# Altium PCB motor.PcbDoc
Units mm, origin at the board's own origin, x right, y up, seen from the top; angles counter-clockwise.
Board outline 22.48 x 19.69 mm, 2 copper layers (Top Layer, Bottom Layer); 9 components, 6 nets, 20 pads, 0 vias.
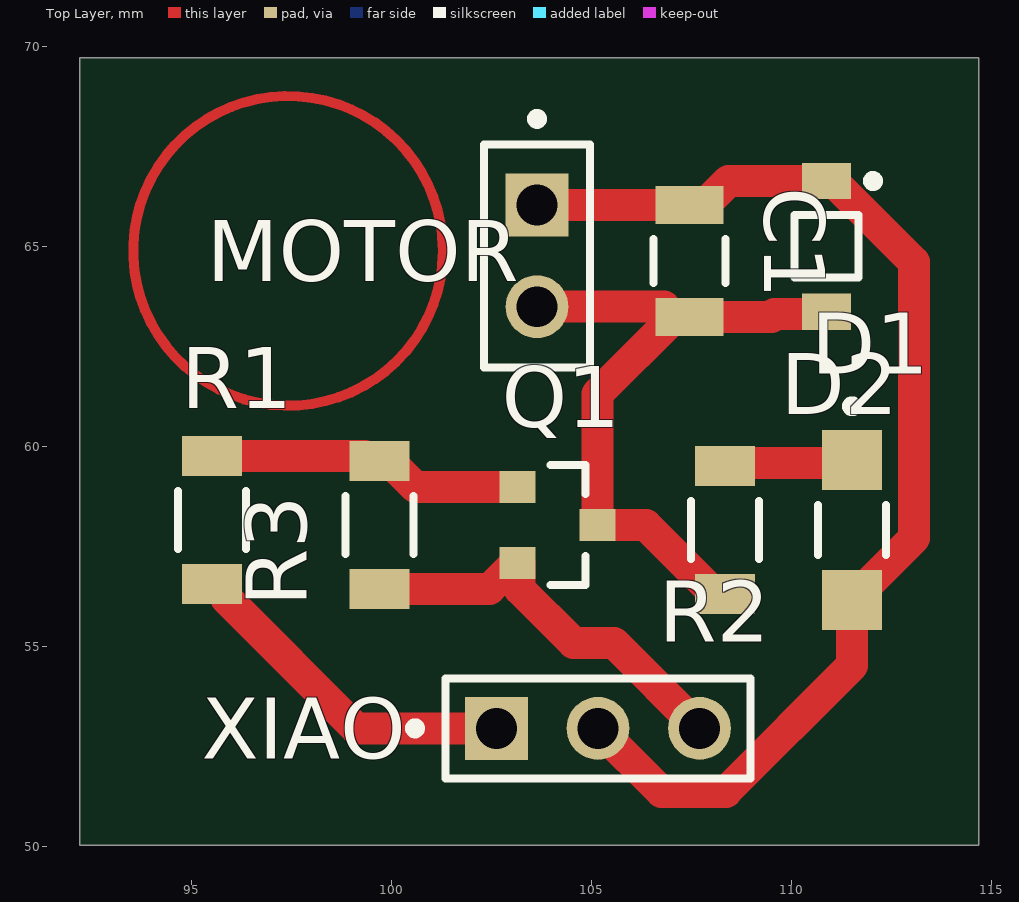
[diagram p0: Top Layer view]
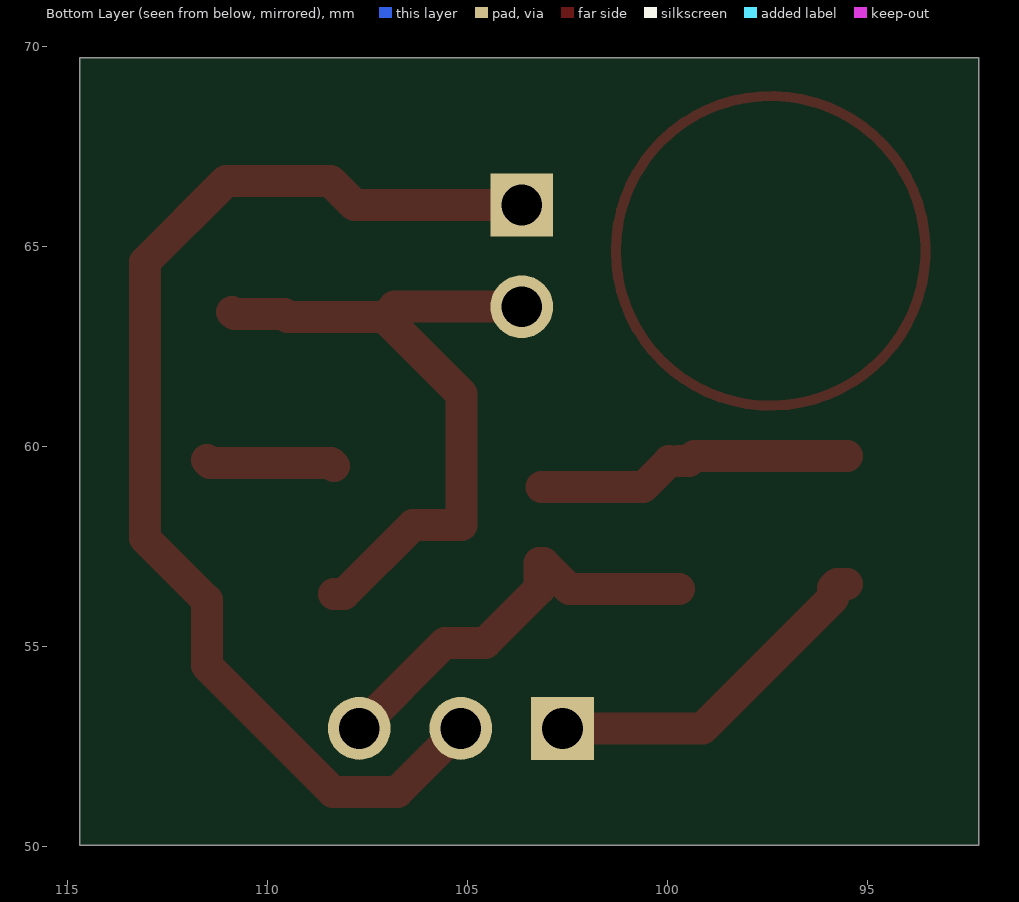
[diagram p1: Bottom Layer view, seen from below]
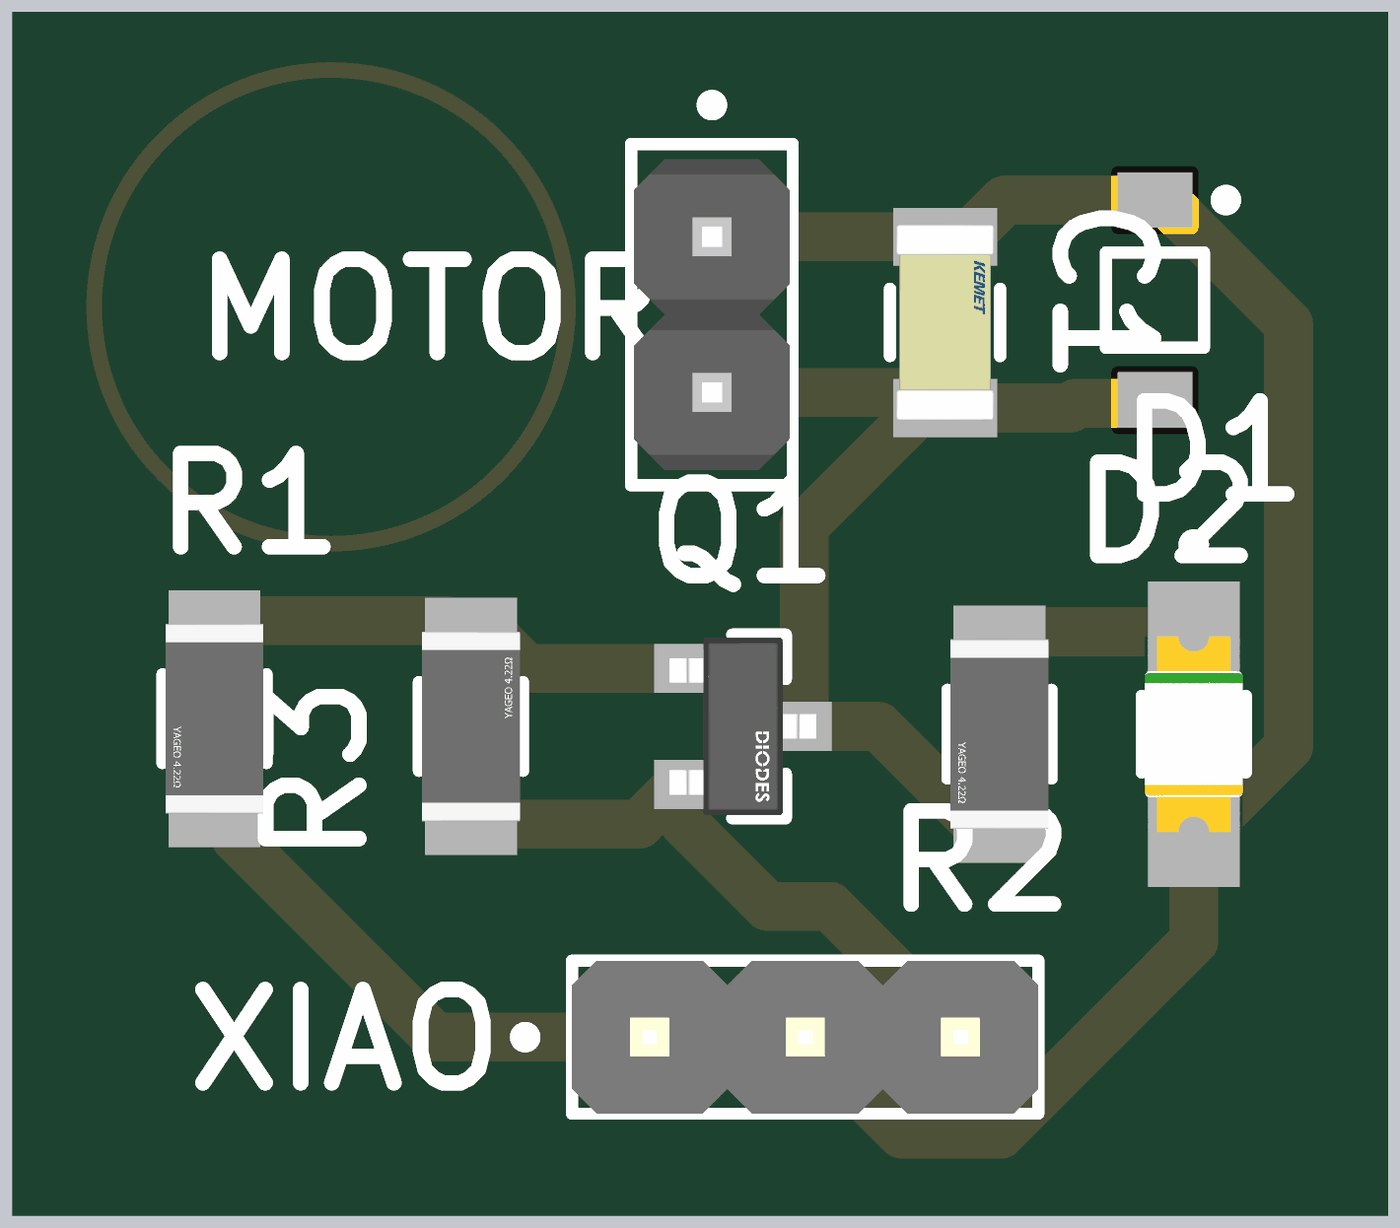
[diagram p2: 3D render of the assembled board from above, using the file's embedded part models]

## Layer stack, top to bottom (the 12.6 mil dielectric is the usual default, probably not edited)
Top Solder: solder mask 0.0102, Solder Resist, Dk 3.5
Top Layer: signal copper 0.0356
Dielectric 1: dielectric 0.32, FR-4, Dk 4.8
Bottom Layer: signal copper 0.0356
Bottom Solder: solder mask 0.0102, Solder Resist, Dk 3.5

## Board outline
92.202,50.038 92.202,69.723 114.681,69.723 114.681,50.038

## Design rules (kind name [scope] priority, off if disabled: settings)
Clearance [All] p1: gap=0.4 ignorepadtopadclearanceinfootprint=FALSE
PolygonConnect [All] p1: connectstyle=Relief reliefconductorwidth=0.254 reliefentries=4 polygonreliefangle="90 Angle" airgapwidth=0.254
RoutingVias [All] p1: holewidth=0.711 width=1.27 viastyle="Through Hole" minholewidth=0.711 minwidth=1.27 maxholewidth=0.711 maxwidth=1.27
SolderMaskExpansion [All] p1: expansion=0.102 istentingtop=FALSE
SupplyNets "Schematic Supply Nets" [InNet('GND')] p1: voltage=0.000
Width [All] p1: maxlimit=0.8 minlimit=0.8 preferedwidth=0.8 minimp=50.000000 maximp=50.000000 favimp=50.000000
30 further rules are at their usual default settings.

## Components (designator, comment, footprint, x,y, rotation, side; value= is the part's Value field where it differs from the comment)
C1 "." FP-C1206C-EB-MFG 107.442,64.643 r270 top value="100 pF"
D1 "LED_2" FP-LTST-C150KSKT-MFG 111.506,57.912 r270 top
D2 "DIODO" ONSC-SOD-123-2-425-04_V 110.871,65.008 r270 top
MOTOR "M20-9990246" FP-M20-9990246-MFG 103.632,64.77 r270 top
Q1 "MOSFET-N" FP-SOT23-MFG 104.14,58.039 r0 top
R1 "." FP-AC1206-MFG 95.504,58.166 r270 top value=2.21KΩ
R2 "." FP-AC1206-MFG 108.331,57.912 r270 top value=2.21KΩ
R3 "." FP-AC1206-MFG 99.695,58.039 r90 top value=2.21KΩ
XIAO "" FP-PR20203VBNN-MFG 105.156,52.959 r0 top

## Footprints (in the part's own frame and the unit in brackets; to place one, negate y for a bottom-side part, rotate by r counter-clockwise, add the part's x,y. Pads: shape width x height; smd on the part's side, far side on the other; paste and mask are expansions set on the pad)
FP-AC1206-MFG [mm]
  rect 1x1.5 smd paste+0 mask+0: 1(-1.6,0) 2(1.6,0)
  silkscreen extent -0.72,-0.85 0.72,0.85, body extent -2.2,-0.95 2.2,0.95, height 0.25
FP-C1206C-EB-MFG [mm]
  rect 0.95x1.7 smd paste+0 mask+0: 1(-1.4,0) 2(1.4,0)
  silkscreen extent -0.55,-0.9 0.55,0.9, body extent -2,-1 2,1, height 0.25
FP-LTST-C150KSKT-MFG [mm]
  rect 1.5x1.5 smd paste+0 mask+0: 1(-1.75,0) 2(1.75,0)
  silkscreen extent -3.22,-0.85 0.63,0.85, body extent -2.6,-0.95 2.6,0.95, height 0.25
FP-M20-9990246-MFG [mm]
  rect 1.57x1.57 hole 1.02 paste-2539.97 mask+0: 1(-1.27,0)
  round 1.57 hole 1.02 paste-2539.97 mask+0: 2(1.27,0)
  silkscreen extent -3.55,-1.32 2.79,1.32, body extent -2.89,-1.42 2.89,1.42, height 0.25
FP-PR20203VBNN-MFG [mm]
  rect 1.57x1.57 hole 1.02 paste-2539.97 mask+0: 1(-2.54,0)
  round 1.57 hole 1.02 paste-2539.97 mask+0: 2(0,0) 3(2.54,0)
  silkscreen extent -4.7,-1.25 3.81,1.25, body extent -3.91,-1.35 3.91,1.35, height 0.25
FP-SOT23-MFG [mm]
  rect 0.9x0.8 smd paste+0 mask+0: 1(-1,0.95) 2(-1,-0.95) 3(1,0)
  silkscreen extent -0.18,-1.5 0.7,1.5, body extent -1.55,-1.6 1.55,1.6, height 0.25
ONSC-SOD-123-2-425-04_V [mm] "SOD, 2-Leads, Body 2.69x1.6mm"
  rect 0.91x1.22 smd: 1(-1.635,0) 2(1.635,0)
  silkscreen extent -1.76,-0.8 0.78,1.29, body extent -1.35,-0.8 1.35,0.8, height 1.35

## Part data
C1: library part CMP-03020-023751-1, "C1206 100 pF X8R 10.00% 50 V", Capacitance="100 pF", Manufacturer=KEMET, Manufacturer Part Number=C1206C101K5HACTU, Package=C1206C-EB, Temperature="-55°C to +150°C", Temperature Characteristic=X8R, Temperature Coefficient=15%, Temperature Range High=+150°C, Temperature Range Low=-55°C, Tolerance=0.1, Voltage Rating="50 V"
D1: library part CMP-2000-06618-2, "LED YELLOW CLEAR 1206 SMD", Case Code (Imperial)=1206, Case Code (Metric)=3216, Color=Yellow, Forward Current=30mA, Forward Voltage=2.4V, Lens Color=Colorless, Max Operating Temperature=85°C, Min Operating Temperature=-55°C, Package Quantity=1, Power Dissipation=75mW, Reverse Voltage=5V, Test Current=20mA
D2: library part CMP-1060-00449-1, "Zener Voltage Regulator, 500 mW, 2-Pin SOD-123, Pb-Free, Tape and Reel", Manufacturer="On Semiconductor", PartNumber=MMSZ5249BT1G
MOTOR: library part CMP-15831-000009-1, "CONN HEADER VERT 2POS 2.54MM", Current Rating=3A, Manufacturer=Harwin, Temperature="-40°C to +105°C", Temperature Range High=+105°C, Temperature Range Low=-40°C
Q1: library part CMP-2000-04929-2, "MOSFET N-CH 60V 115MA SOT23-3", Case/Package=SOT-23, Continuous Drain Current (ID)=115mA, Drain to Source Breakdown Voltage=70V, Drain to Source Resistance=7.5R, Drain to Source Voltage (Vdss)=60V, Gate to Source Voltage (Vgs)=20V, Input Capacitance=50pF, Max Operating Temperature=150°C, Max Power Dissipation=300mW, Min Operating Temperature=-55°C, Package Quantity=3000, Power Dissipation=540mW, Threshold Voltage=2.5V
R1 R2 R3: library part CMP-03412-032679-1, "RES SMD 2.21K OHM 1% 1/4W 1206", Manufacturer=Yageo, Manufacturer Part Number=AC1206FR-072K21L, Package=AC1206, Power Rating=0.25W, Resistance=2.21KΩ, Temperature="-55°C to +155°C", Temperature Range High=+155°C, Temperature Range Low=-55°C, Tolerance=0.01, Voltage Rating=200V
XIAO: library part CMP-77940-000002-1, "CONN HEADER VERT 3POS 2.54MM", Current Rating=3A, Manufacturer="Metz Connect", Manufacturer Part Number=PR20203VBNN, Temperature="-40°C to +105°C", Temperature Range High=+105°C, Temperature Range Low=-40°C

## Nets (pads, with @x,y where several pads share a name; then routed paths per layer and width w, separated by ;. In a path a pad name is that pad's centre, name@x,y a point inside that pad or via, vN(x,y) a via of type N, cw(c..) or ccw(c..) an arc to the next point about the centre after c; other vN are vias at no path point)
3V3: C1.1 D1.2 D2.1 MOTOR.1 XIAO.2 | length 29.6
  Top Layer w0.8: MOTOR.1 103.634,66.042 107.441,66.042 C1.1 107.817,66.043 108.417,66.643 D2.1 111.026,66.643 113.056,64.613 113.056,57.712 D1.2 111.506,54.527 108.353,51.374 106.741,51.374 XIAO.2
D1: R1.2 XIAO.1 | length 8.8
  Top Layer w0.8: R1.2 95.754,56.566 95.854,56.466 95.854,56.216 99.111,52.959 XIAO.1
GND: Q1.2 R3.1 XIAO.3 | length 10.4
  Top Layer w0.8: R3.1 102.44,56.439 103.09,57.089 103.19,57.089 103.19,56.449 104.541,55.098 105.557,55.098 XIAO.3
Motor_azul: C1.2 D2.2 MOTOR.2 Q1.3 R2.2 | length 17.3
  Top Layer w0.8: MOTOR.2 106.81,63.5 C1.2@107.067,63.243 ; R2.2 108.081,56.312 106.354,58.039 Q1.3 105.14,61.316 C1.2@107.067,63.243 ; D2.2 110.816,63.318 109.567,63.318 109.492,63.243 C1.2 C1.2@107.067,63.243
NetD1_1: D1.1 R2.1 | length 3.2
  Top Layer w0.8: R2.1 108.406,59.587 111.431,59.587 D1.1
NetQ1_1: Q1.1 R1.1 R3.2 | length 7.7
  Top Layer w0.8: R1.1 99.318,59.766 99.445,59.639 R3.2 ; R3.2@99.945,59.639 100.595,58.989 Q1.1
copper on no net: | length 24.3
  Top Layer w0.254: 101.28,64.897 ccw(c97.409,64.897) 101.28,64.897

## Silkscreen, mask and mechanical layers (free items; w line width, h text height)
Mechanical 1:
  the board outline again, w1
